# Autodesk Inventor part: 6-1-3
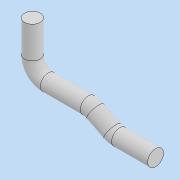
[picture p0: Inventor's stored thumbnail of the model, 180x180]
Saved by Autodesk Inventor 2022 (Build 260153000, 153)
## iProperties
Created: 2021-07
Part Number: 6-1-3
Material: 一般
Document SubType Name: Modeling
Designer: DesignLab
Density: 1 g/cm^3
Appearance: 既定
Author: DesignLab
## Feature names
1. スイープ1
## Parameters: d2 = 75 mm, d4 = 15 mm, d5 = 155 mm, d7 = 0, d8 = 0
